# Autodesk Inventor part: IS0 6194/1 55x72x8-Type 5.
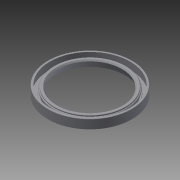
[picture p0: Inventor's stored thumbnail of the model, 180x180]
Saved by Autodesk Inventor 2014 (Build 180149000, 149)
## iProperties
Shininess: 20.0
Length Units: 11269
Angle Units: 11279
Time Units: 11290
Mass Units: 11283
Length Display Precision: 3
Angle Display Precision: 2
Created: 2001-02
Part Number: IS0 6194/1 55x72x8-Type 5.
Material: Delrin, Black
Description: Sealing IS0 6194/1 55x72x8 Type 5.
Document SubType Name: Modeling
Designer: Roman
Density: 1.425 g/cm^3
Appearance: Default
Density: 1.425
Volumn: 3.6609660845694885
Area: 66.70931044186776
PropertySet Name: Model Information
Control State: 0
Master: False
Checked Out: False
BOM1: Sealing
BOM2: 55x72x8-Type 5
BOM3: IS0 6194/1
ProtocolID: P00020918090936065
Protocol: P00020918090936065<@PID>[Version]<@EL>Version=2.2<@EL>[Synchronize]<@EL>ChangedVars=<@EL>[Data]<@EL>d=55{mm<@EL>dd=72{mm<@EL>b=8{mm<@EL>mass=0.021{kg<@EL>MSP_PP
Author: PaulN
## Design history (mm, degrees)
node "WorkPlane2"
node "Sketch1"
node "WorkPoint1"
node "WorkPlane3"
sketch "Sketch2"
  geometry: L1 (34.3, -0.4)-(35.2, -0.4); L2 (34.3, 0)-(34.3, -0.4); L3 (36, 0)-(34.3, 0); L4 (36, -8)-(36, 0); L5 (30.016, -8)-(36, -8); L6 (28.954, -4.8)-(30.016, -8); L7 (28.181, -4.251)-(28.954, -4.8); L8 (27.5, -2.2)-(28.181, -4.251); L9 (28.395, -1.2)-(27.5, -2.2); L10 (30.52, -1.2)-(28.395, -1.2); L11 (30.52, -2.2)-(30.52, -1.2); L12 (30.52, -6.4)-(30.52, -3.8); L13 (31.653, -6.4)-(30.52, -6.4); L14 (31.653, -7.2)-(31.653, -6.4); L15 (35.2, -7.2)-(31.653, -7.2); L16 (35.2, -0.4)-(35.2, -7.2); L17 (0, -15.959)-(0, 2.029); L18 (0, -15.959)-(0, 2.029); L19 (0, -19.557)-(0, 5.626) reference; L20 (-7.2, 0)-(43.2, 0) reference; A1 r 0.8 centre (30.52, -3) between (30.52, -3.8) and (30.52, -2.2)
  constraints: 36 end point, 7 vertical, 6 horizontal, 2 collinear, 2 point on circle, 1 centre point, 1 parallel, 1 point on line
  dimensions: "d2" = 0.4 distance of L2.start L1.start (= 0.05 x prf_b); "d4" = 8 distance of L4.start L3.start (= prf_b); "d6" = 0.8 horizontal distance of L1.end L3.start (= 0.1 x prf_b); "d8" = 0.8 horizontal distance of L15.start L4.start (= 0.1 x prf_b); "d10" = 0.8 distance of L14.start L13.start (= 0.1 x prf_b); "d12" = 0.8 vertical distance of L1.end L10.start (= 0.1 x prf_b); "d14" = 1 distance of L11.start L10.start (= 0.125 x prf_b); "d16" = 0.8 radius of A1 (= 0.1 x prf_b); "d18" = 0 horizontal distance of A1.centre L12.end; "d20" = 1 vertical distance of L9.start L8.start (= 0.125 x prf_b); "d22" = 2.05128 vertical distance of L8.start L7.start (= 0.25641 x prf_b); "d24" = 3.2 vertical distance of L6.start L5.start (= 0.4 x prf_b); "d26" = 1.7 distance of L3.start L2.start (= 0.1 x prf_dd - 0.1 x prf_d); "d28" = 0.89474 horizontal distance of L9.start L8.start (= 0.0526316 x prf_dd - 0.0526316 x prf_d); "d30" = 2.125 distance of L10.start L9.start (= 0.125 x prf_dd - 0.125 x prf_d); "d32" = 1.13333 distance of L13.start L12.start (= 0.0666667 x prf_dd - 0.0666667 x prf_d); "d34" = 1.0625 horizontal distance of L6.start L5.start (= 0.0625 x prf_dd - 0.0625 x prf_d); "d36" = 0.77273 horizontal distance of L7.start L6.start (= 0.0454545 x prf_dd - 0.0454545 x prf_d); "msp_d39" = 55 diameter of L8.start L17 (= prf_d); "msp_d40" = 72 diameter of L4 L17 (= prf_dd)
revolve "RevolutionFull1" sketch "Sketch2" stored, may be unused: angle "d37" = 360 deg
fillet "Fillet1" dims "d38" = 0.4 (= 0.05 x prf_b)
body "Solid1"
other parameters: "prf_dd" = 72 [user parameter; used in 7 equation terms], "prf_d" = 55 [user parameter; used in 7 equation terms], "prf_b" = 8 [user parameter; used in 13 equation terms], "d0" = -8 (computed from prf_b), "d1" = 0.4 (derived), "d3" = 8 (derived), "d5" = 0.8 (derived), "d7" = 0.8 (derived), "d9" = 0.8 (derived), "d11" = 0.8 (derived), "d13" = 1 (derived), "d15" = 0.8 (derived), "d17" = 0 (derived), "d19" = 1 (derived), "d21" = 2.05128 (derived), "d23" = 3.2 (derived), "d25" = 2 (derived), "d27" = 1.05263 (derived), "d29" = 2.5 (derived), "d31" = 1.33333 (derived), "d33" = 1.25 (derived), "d35" = 0.90909 (derived), "d42" = 0
